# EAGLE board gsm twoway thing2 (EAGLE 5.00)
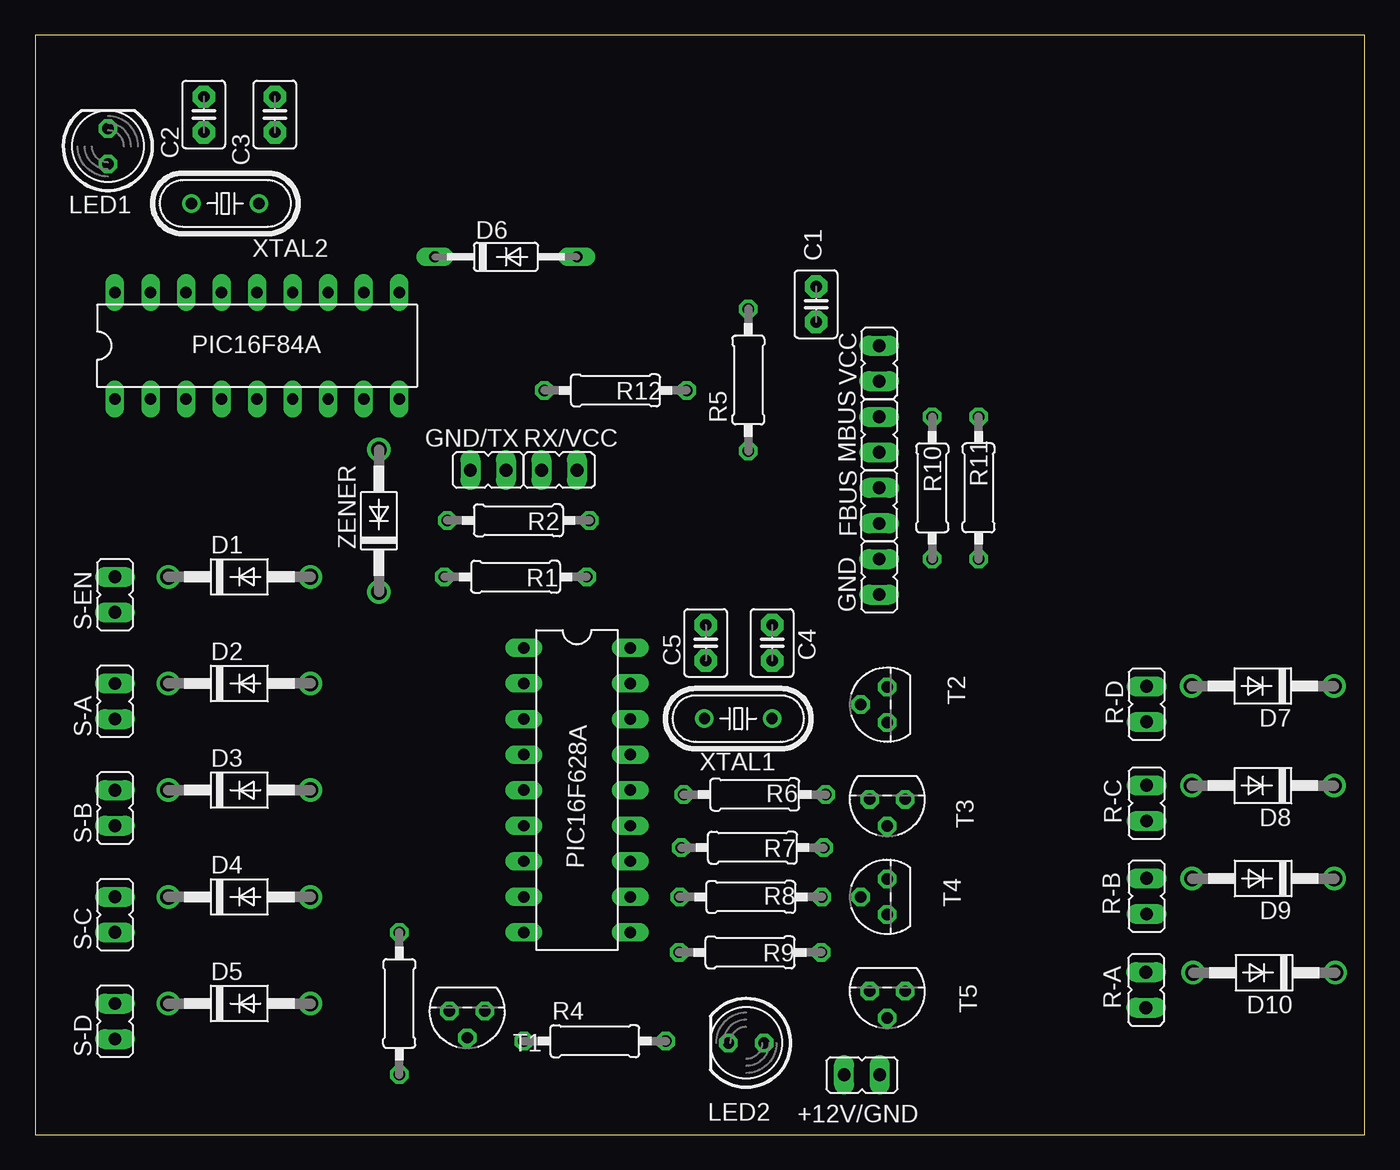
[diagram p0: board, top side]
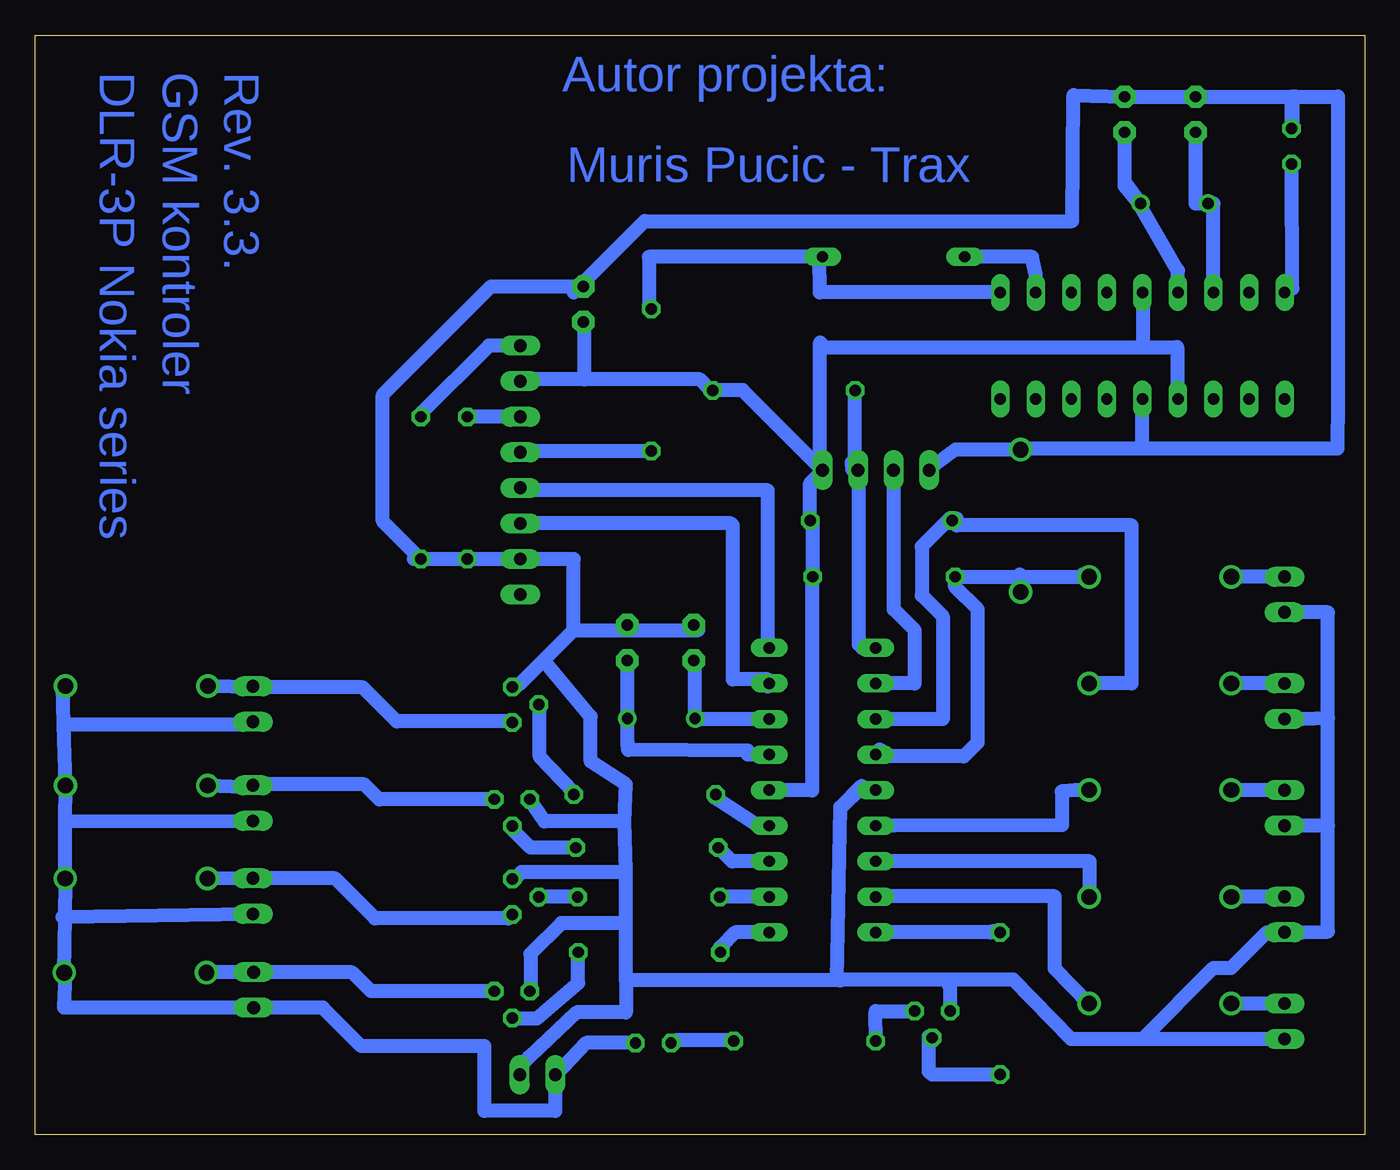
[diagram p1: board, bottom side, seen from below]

Size 95 x 78.54 mm. Coordinates in mm from the lower left corner, seen from the top.
Outline: 0,0 95,0 95,78.54 0,78.54 0,0
Copper layers (1*16): Top 0.035mm / dielectric 1.5mm / Bottom 0.035mm
Design rules "default *": minimum track width 1mm, minimum drill 24mil, track to track 0.7mm, track to pad 0.7mm, pad to pad 8mil, via to via 8mil, smd to smd 8mil, copper to edge 40mil, drill to drill 8mil, minimum pad ring 10mil, minimum via ring 8mil, stop-mask expansion 4mil, vias tented up to drill 0mil, thermal gap 10mil

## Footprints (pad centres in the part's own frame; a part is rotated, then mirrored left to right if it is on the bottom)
JP1 = drill 0.914 long: 1 0,-1.27; 2 0,1.27
C2.5-3 = drill 0.813 pad 1.6 octagon: 1 -1.27,0; 2 1.27,0
DO41-10 = drill 1.118 round: A 5.08,0; C -5.08,0
DO35-10 = drill 0.813 long: A 5.08,0; C -5.08,0
LED5MM = drill 0.813 octagon: A -1.27,0; K 1.27,0
DIL18 = drill 0.813 long: 1 -10.16,-3.81; 2 -7.62,-3.81; 3 -5.08,-3.81; 4 -2.54,-3.81; 5 0,-3.81; 6 2.54,-3.81; 7 5.08,-3.81; 8 7.62,-3.81; 9 10.16,-3.81; 10 10.16,3.81; 11 7.62,3.81; 12 5.08,3.81; 13 2.54,3.81; 14 0,3.81; 15 -2.54,3.81; 16 -5.08,3.81; 17 -7.62,3.81; 18 -10.16,3.81
0207/10 = drill 0.813 octagon: 1 -5.08,0; 2 5.08,0
TO92 = drill 0.813 octagon: 1 1.27,0; 2 0,1.905; 3 -1.27,0
HC49/S = drill 0.813 round: 1 -2.413,0; 2 2.413,0

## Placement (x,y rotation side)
+12V/GND  [JP1]  59.09,4.27 90 top
C1  1nF  [C2.5-3]  55.81,59.31 90 top
C2  22pF  [C2.5-3]  12.06,72.86 90 top
C3  22pF  [C2.5-3]  17.14,72.86 90 top
C4  22pF  [C2.5-3]  52.67,35.12 90 top
C5  22pF  [C2.5-3]  47.93,35.12 90 top
D1  1N4001  [DO41-10]  14.6,39.84 0 top
D2  1N4001  [DO41-10]  14.6,32.22 0 top
D3  1N4001  [DO41-10]  14.6,24.6 0 top
D4  1N4001  [DO41-10]  14.6,16.98 0 top
D5  1N4001  [DO41-10]  14.6,9.36 0 top
D6  1N4148  [DO35-10]  33.65,62.7 0 top
D7  1N4004  [DO41-10]  87.73,32.04 180 top
D8  1N4004  [DO41-10]  87.74,24.93 180 top
D9  1N4004  [DO41-10]  87.76,18.29 180 top
D10  1N4004  [DO41-10]  87.83,11.56 180 top
FBUS  [JP1]  60.32,44.92 180 top
GND  [JP1]  60.32,39.84 0 top
GND/TX  [JP1]  32.38,47.46 270 top
LED1  [LED5MM]  5.21,70.59 90 top
LED2  [LED5MM]  50.82,6.55 180 top
MBUS  [JP1]  60.32,50 0 top
PIC16F84A  [DIL18]  15.87,56.35 0 top
PIC16F628A  [DIL18]  38.73,24.6 270 top
R1  4k7  [0207/10]  34.34,39.84 180 top
R2  4k7  [0207/10]  34.54,43.87 180 top
R3  4k7  [0207/10]  26.03,9.36 270 top
R4  1k  [0207/10]  40,6.67 0 top
R5  150R  [0207/10]  50.97,53.9 90 top
R6  4k7  [0207/10]  51.43,24.29 0 top
R7  4k7  [0207/10]  51.27,20.49 0 top
R8  4k7  [0207/10]  51.15,16.97 0 top
R9  4k7  [0207/10]  51.1,13.02 0 top
R10  1k  [0207/10]  64.11,46.19 270 top
R11  15k  [0207/10]  67.42,46.19 90 top
R12  4k7  [0207/10]  41.48,53.16 0 top
R-A  [JP1]  79.38,10.33 0 top
R-B  [JP1]  79.43,17.03 0 top
R-C  [JP1]  79.43,23.67 0 top
R-D  [JP1]  79.43,30.75 0 top
RX/VCC  [JP1]  37.46,47.46 270 top
S-A  [JP1]  5.71,30.95 0 top
S-B  [JP1]  5.71,23.33 0 top
S-C  [JP1]  5.71,15.71 0 top
S-D  [JP1]  5.71,8.09 0 top
S-EN  [JP1]  5.71,38.57 0 top
T1  BC547  [TO92]  30.88,8.82 180 top
T2  BC547  [TO92]  60.9,30.71 90 top
T3  BC547  [TO92]  60.9,23.95 180 top
T4  BC547  [TO92]  60.9,16.98 90 top
T5  BC547  [TO92]  60.9,10.24 180 top
VCC  [JP1]  60.32,55.08 0 top
XTAL1  [HC49/S]  50.25,29.71 0 top
XTAL2  8 MHz  [HC49/S]  13.6,66.51 0 top
ZENER  5 V  [DO41-10]  24.58,43.84 90 top

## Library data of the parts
+12V/GND FBUS GND GND/TX MBUS R-A R-B R-C R-D RX/VCC S-A S-B S-C S-D S-EN VCC = jumper
C1-C5 = capacitor-wima
D1-D10 ZENER = diode
LED1 LED2 = led
PIC16F84A PIC16F628A = ic-package
R1-R12 = resistor
T1-T5 = transistor-npn
XTAL1 XTAL2 = crystal

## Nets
GND: +12V/GND.1 C1.2 C2.2 C3.2 C4.2 C5.2 GND.2 GND/TX.1 LED1.K PIC16F84A.5 PIC16F628A.5 R10.2 R11.1 S-A.1 S-B.1 S-C.1 S-D.1 S-EN.1 T1.1 T2.1 T3.1 T4.1 T5.1 ZENER.A
N$1: C4.1 PIC16F628A.15 XTAL1.2
N$2: C5.1 PIC16F628A.16 XTAL1.1
N$3: PIC16F628A.13 R6.1
N$4: PIC16F628A.12 R7.1
N$5: PIC16F628A.11 R8.1
N$6: PIC16F628A.10 R9.1
N$7: R6.2 T2.2
N$8: R9.2 T5.2
N$9: R8.2 T4.2
N$10: R7.2 T3.2
N$11: D5.A PIC16F628A.8
N$12: D4.A PIC16F628A.7
N$13: D3.A PIC16F628A.6
N$14: D1.A PIC16F628A.4 R1.2 ZENER.C
N$15: D2.A PIC16F628A.3 R2.2
N$16: R4.1 T1.3
N$17: GND/TX.2 PIC16F628A.2
N$18: PIC16F628A.1 R12.1 RX/VCC.1
N$19: D5.C S-D.2
N$20: C1.1 PIC16F84A.4 PIC16F84A.14 PIC16F628A.14 R1.1 R2.1 R12.2 RX/VCC.2 VCC.1
N$21: PIC16F628A.9 R3.1
N$22: R3.2 T1.2
N$23: LED2.K R4.2
N$24: R11.2 VCC.2
N$25: MBUS.2 R10.1
N$26: D10.A R-A.2 T5.3
N$27: D9.A R-B.2 T4.3
N$28: D8.A R-C.2 T3.3
N$29: D7.A R-D.2 T2.3
N$30: C3.1 PIC16F84A.15 XTAL2.2
N$31: C2.1 PIC16F84A.16 XTAL2.1
N$32: MBUS.1 R5.1
N$33: D4.C S-C.2
N$34: D6.A PIC16F84A.10 R5.2
N$35: D6.C PIC16F84A.11
N$36: FBUS.2 PIC16F628A.17
N$37: FBUS.1 PIC16F628A.18
N$38: D3.C S-B.2
N$39: D1.C S-EN.2
N$40: D2.C S-A.2
N$41: LED1.A PIC16F84A.18
N$42: +12V/GND.2 D7.C D8.C D9.C D10.C LED2.A R-A.1 R-B.1 R-C.1 R-D.1

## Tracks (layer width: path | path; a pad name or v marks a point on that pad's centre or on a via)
GND
  Bottom 1: +12V/GND.1 60.32,4.28 | +12V/GND.1 60.36,4.11 | 31.13,47.51 31.11,47.49 | 31.13,47.51 29.22,48.92 ZENER.A 24.58,48.96 24.62,49 | R10.2 63.88,41.11 63.88,41.07 | R10.2 R11.1 67.94,41.11 67.69,41.36 | GND.2 R10.2 | 60.25,41.07 60.25,41.11 GND.2 | 67.69,41.36 67.4,41.07 | 67.69,41.36 70.15,43.82 70.15,52.84 62.41,60.58 C1.2 56.51,60.16 51.43,65.24 20.88,65.24 20.79,74.24 C3.2 C2.2 5.17,74.13 5.16,71.92 LED1.K 5.21,74 5.25,73.96 4.92,74.13 | 2.62,22.06 2.62,14.5 4.44,14.44 S-C.1 6.98,14.44 9.52,11.9 10.79,11.9 15.87,6.82 | 2.62,22.06 S-B.1 | 2.62,29.74 4.44,29.68 S-A.1 | 2.62,29.74 2.62,37.3 S-EN.1 | 2.62,22.06 2.62,29.74 | 37.46,23.33 36.19,24.6 PIC16F628A.5 | 37.68,11.07 37.46,23.33 | 29.78,11.07 25.09,11.07 20.95,6.82 15.87,6.82 | 29.78,11.07 37.68,11.07 | S-D.1 15.87,6.82 | 58.66,33.88 56.51,36.03 | 58.66,33.88 60.32,32.22 T2.1 | 56.51,36.03 52.7,36.03 | 52.7,36.03 47.62,36.03 C5.2 | 52.7,36.03 C4.2 | 56.51,36.03 56.51,41.11 GND.2 | 31.13,47.51 GND/TX.1 | +12V/GND.1 60.25,4.99 59.7,5.54 56.29,8.73 52.77,8.73 52.77,11.04 | 52.77,11.04 52.77,15.11 | 52.77,15.11 57.39,15.11 59.59,12.91 59.59,10.16 59.63,10.2 T5.1 | T4.1 60.74,18.25 60.25,18.74 52.88,18.74 | 52.88,18.74 52.77,18.74 52.77,15.11 | T3.1 59.3,23.4 58.6,22.37 52.88,22.37 | 52.88,22.37 52.77,18.85 52.88,18.74 | 52.88,22.37 52.77,25.01 55.3,26.66 55.3,29.85 58.66,33.88 | 37.46,23.33 37.4,23.33 35.94,24.79 | 37.46,23.33 37.46,23.38 35.94,24.9 | 37.59,11.04 37.37,11.04 | 37.59,11.04 52.77,11.04 | 52.77,11.04 52.55,10.93 | 37.68,11.07 37.46,11.02 37.59,11.04 | 4.92,74.13 1.9,74.13 1.9,52.54 1.94,49 15.87,49 | 4.92,74.13 5.02,74.13 | 15.87,49 PIC16F84A.5
  Bottom 1: 15.87,49 24.62,49 | 24.62,49 24.63,49.01 | 29.78,11.07 29.67,10.6 29.61,10.54 T1.1
N$1
  Bottom 1: 52.66,33.92 52.67,33.91 C4.1 | 52.66,33.92 XTAL1.2 52.66,29.63 52.66,27.98 52.62,27.47 44.08,27.43 44.08,27.14 PIC16F628A.15 | 52.66,33.92
N$2
  Bottom 1: PIC16F628A.16 47.76,29.68 47.82,29.74 47.84,29.72 XTAL1.1 47.84,33.83 47.93,33.92 C5.1
N$3
  Bottom 1: 46.46,24.09 46.17,23.91 | 46.46,24.09 R6.1 | PIC16F628A.13 43.33,22.06 46.46,24.09
N$4
  Bottom 1: R7.1 46.17,20.5 45.19,19.52 PIC16F628A.12
N$5
  Bottom 1: R8.1 45.85,16.97 45.84,16.98 PIC16F628A.11
N$6
  Bottom 1: 46.02,13.39 46.06,13.35 | 46.02,13.39 R9.1 | PIC16F628A.10 44.97,14.44 46.02,13.39
N$7
  Bottom 1: R6.2 56.51,24.46 58.93,26.99 58.93,30.4 58.82,30.62 58.91,30.71 T2.2
N$8
  Bottom 1: R9.2 56.18,10.82 59.15,8.29 60.91,8.29 60.9,8.3 T5.2
N$9
  Bottom 1: 59,16.8 59.04,16.76 | 59,16.8 T4.2 | R8.2 58.83,16.97 59,16.8
N$10
  Bottom 1: T3.2 60.8,21.71 59.58,20.49 R7.2
N$11
  Bottom 1: D5.A 22.13,11.86 22.13,17.01 34.63,17.01 34.63,16.98 PIC16F628A.8
N$12
  Bottom 1: D4.A 19.63,17.48 19.63,19.51 34.63,19.51 34.64,19.52 PIC16F628A.7
N$13
  Bottom 1: D3.A 20.63,24.6 21.63,24.51 21.61,22.1 33.65,22.06 PIC16F628A.6
N$14
  Bottom 1: D1.A 19.96,39.84 20.13,40.01 20.3,39.84 24.63,39.84 | 24.63,39.84 R1.2 29.26,39.14 27.63,37.51 27.63,28.01 28.63,27.01 34.13,27.01 34.63,27.51 34.92,27.22 PIC16F628A.4 | 24.63,39.84 24.63,40.01 24.58,39.96 ZENER.C
N$15
  Bottom 1: 19.95,32.22 D2.A 16.63,32.22 16.63,43.51 29.13,43.51 29.13,43.87 | 29.13,43.87 29.13,44.01 | 29.13,43.87 R2.2 29.49,43.87 29.63,44.01 31.63,42.01 31.63,38.51 30.13,37.01 30.13,29.68 PIC16F628A.3
N$16
  Bottom 1: R4.1 34.94,8.76 34.8,8.79 34.94,8.82 T1.3
N$17
  Bottom 1: PIC16F628A.2 32.13,32.22 32.13,36.01 33.63,37.51 33.63,47.46 | 33.63,47.46 33.63,47.51 | 33.63,47.46 GND/TX.2
N$18
  Bottom 1: 36.63,48.01 36.58,47.46 RX/VCC.1 36.13,47.51 | R12.1 36.4,47.78 36.13,47.51 | PIC16F628A.1 35.88,34.76 36.13,35.01 36.13,47.51
N$19
  Bottom 1: S-D.2 D5.C
N$20
  Bottom 1: PIC16F628A.14 39.49,24.6 39.46,24.57 39.46,39.75 39.37,39.84 | 39.37,39.84 39.35,39.86 | 39.37,39.84 R1.1 39.42,43.78 39.51,43.87 R2.1 39.62,46.52 38.69,47.45 38.7,47.46 | 38.7,47.46 RX/VCC.2 44.44,53.17 R12.2 | R12.2 46.72,53.17 47.49,53.94 55.74,53.94 | R12.2 | PIC16F84A.4 13.39,52.6 13.39,56.25 15.7,56.25 | 15.7,56.25 15.81,56.25 15.81,60.22 | 15.81,60.22 15.81,60.43 | 15.81,60.22 PIC16F84A.14 | 38.7,47.46 38.91,47.67 38.91,56.58 38.58,56.25 15.7,56.25 | VCC.1 60.25,53.88 60.25,53.94 55.74,53.94 | C1.1 55.74,57.97 55.74,53.94
N$21
  Bottom 1: PIC16F628A.9 26.7,14.44 26.63,14.51 26.13,14.51 26.06,14.44 R3.1
N$22
  Bottom 1: R3.2 30.9,4.28 31.13,4.51 31.13,7.01 31.04,6.91 T1.2
N$23
  Bottom 1: R4.2 45.41,6.72 49.22,6.72 LED2.K
N$24
  Bottom 1: R11.2 67.42,51.32 67.51,51.41 62.57,56.35 VCC.2
N$25
  Bottom 1: R10.1 64.11,51.29 64.1,51.3 64.07,51.27 MBUS.2
N$26
  Bottom 1: D10.A 82.58,11.59 R-A.2 | 79.72,11.59 R-A.2 | T5.3 71,10.24 72.35,11.59 78.95,11.59 79.06,11.48 79.18,11.6 R-A.2
N$27
  Bottom 1: D9.A 79.28,18.3 R-B.2 73.56,18.3 70.7,15.44 61.17,15.44 T4.3
N$28
  Bottom 1: R-C.2 79.28,24.79 D8.A | 79.5,24.79 79.43,24.86 R-C.2 | T3.3 70.41,23.95 71.47,25.01 79.5,25.01 R-C.2
N$29
  Bottom 1: D7.A 79.39,31.94 R-D.2 79.35,31.94 71.58,31.94 69.16,29.52 60.98,29.52 T2.3
N$30
  Bottom 1: 16.14,66.51 17.14,67.74 | 16.14,66.51 17.14,68.01 | 17.14,68.01 C3.1 | 17.14,68.01 XTAL2.2 | 16.14,66.51 16.13,66.51 13.33,61.71 PIC16F84A.15
N$31
  Bottom 1: 12.06,66.51 10.79,66.51 PIC16F84A.16 | 12.06,66.51 C2.1 | 12.06,66.51 XTAL2.1
N$32
  Bottom 1: MBUS.1 60.36,48.73 60.36,48.82 R5.1
N$33
  Bottom 1: S-C.2 D4.C
N$34
  Bottom 1: PIC16F84A.10 38.92,60.16 38.96,62.7 D6.A 51.13,62.7 51.13,59.2 | 51.13,59.2 51.13,59.01 | 51.13,59.2 R5.2
N$35
  Bottom 1: PIC16F84A.11 23.49,61.43 23.76,62.7 D6.C
N$36
  Bottom 1: FBUS.2 45.27,43.65 45.13,43.51 45.13,32.51 42.63,32.51 42.63,32.01 42.54,32.1 PIC16F628A.17
N$37
  Bottom 1: PIC16F628A.18 42.63,35.67 42.63,46.01 60.14,46.01 FBUS.1
N$38
  Bottom 1: S-B.2 D3.C
N$39
  Bottom 1: S-EN.2 D1.C
N$40
  Bottom 1: S-A.2 D2.C
N$41
  Bottom 1: LED1.A 5.16,60.43 5.21,60.43 PIC16F84A.18
N$42
  Bottom 1: 57.82,4.23 57.83,4.22 | 57.82,4.23 +12V/GND.2 57.83,1.69 62.89,1.69 62.89,6.31 71.69,6.31 74.44,9.06 79.28,9.06 79.38,9.16 | LED2.A 55.61,6.55 57.82,4.23 | 92.85,15.55 92.81,18.08 D9.C 92.82,22.37 | 92.85,15.55 D10.C 92.81,11.48 92.92,9.06 R-A.1 79.38,9.16 | 92.82,22.37 92.81,24.9 D8.C 92.95,29.3 | D7.C 93.03,32.05 92.95,29.3 | R-D.1 79.06,29.3 92.92,29.3 92.95,29.3 | 92.82,22.37 92.7,22.37 R-C.1 | 92.85,15.55 93.03,15.55 R-B.1 | 79.38,9.16 79.39,9.17

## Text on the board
Bottom: Rev. 3.3. | GSM kontroler | DLR-3P Nokia series | Autor projekta: | Muris Pucic - Trax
